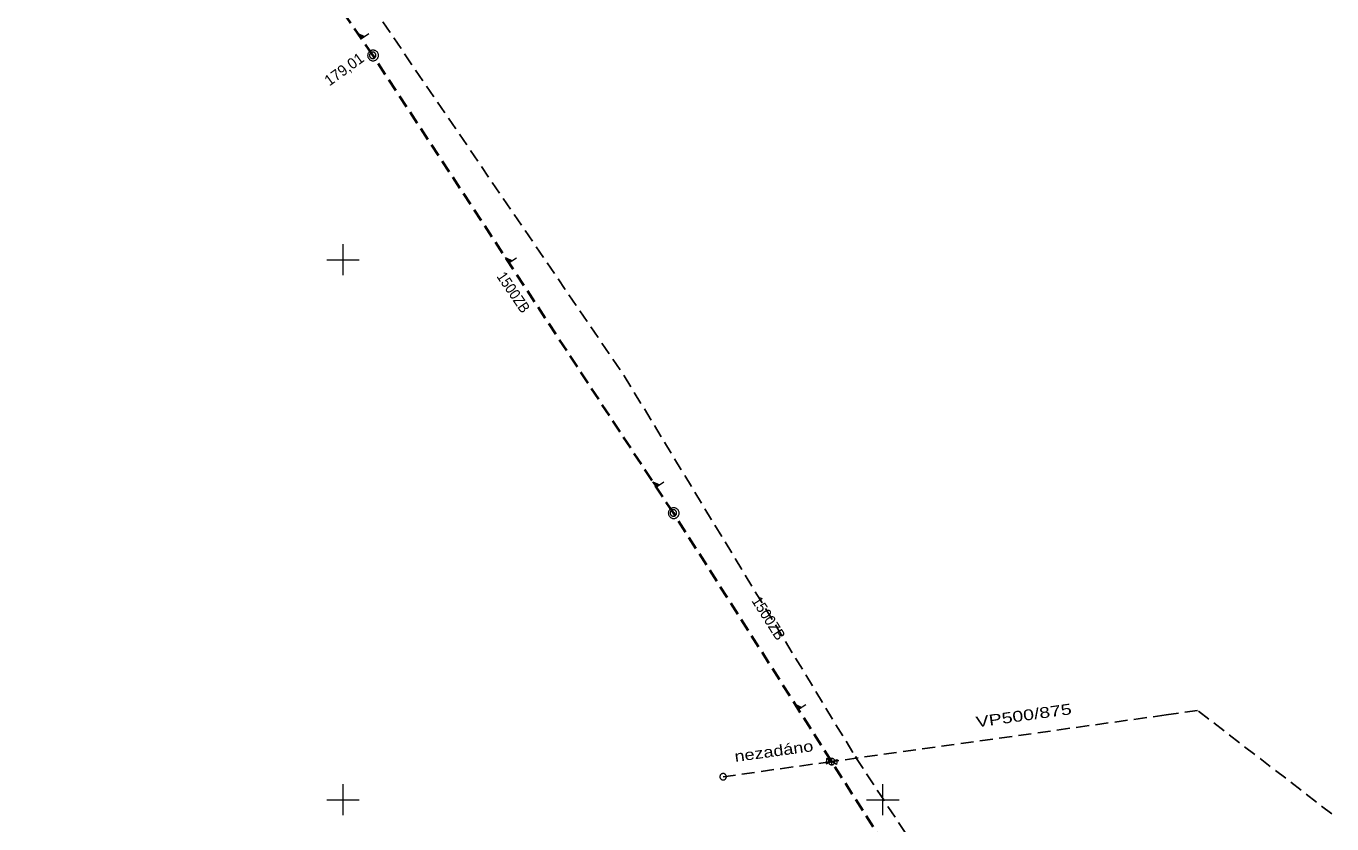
# Model space of a CAD drawing. Extents: x -740851 to -738888, y -1041382 to -1040235.
# Drawn here: x -739579.3 to -739458.4, y -1040852.2 to -1040778.4 of the extents above; entities that cross this region are included whole.
import ezdxf

# ---------------------------------------------------------------- set-up
doc = ezdxf.new("R2010")
doc.units = 0
doc.header["$LTSCALE"] = 0.4
doc.linetypes.add('MEDIUM_DASHED', pattern=[4.5, 3, -1.5])
for name, color, linetype, lineweight in [('1', 7, 'Continuous', 13), ('18', 7, 'Continuous', 13), ('19', 7, 'Continuous', 25), ('8', 7, 'Continuous', 13)]:
    doc.layers.add(name, color=color, linetype=linetype, lineweight=lineweight)

msp = doc.modelspace()

# ---------------------------------------------------------------- linework, layer by layer
at = {"layer": '1'}
for p, q in [((-739550, -1040798.571), (-739550, -1040801.429)), ((-739551.48, -1040800), (-739548.48, -1040800)), ((-739550, -1040848.571), (-739550, -1040851.429)), ((-739500, -1040848.571), (-739500, -1040851.429)), ((-739551.48, -1040850), (-739548.48, -1040850)), ((-739501.48, -1040850), (-739498.48, -1040850))]:
    msp.add_line(p, q, dxfattribs=at)
at = {"layer": '18', "linetype": 'MEDIUM_DASHED', "lineweight": 40}
for p, q in [((-739547.23, -1040781.07), (-739576.27, -1040738.69)), ((-739519.38, -1040823.45), (-739547.23, -1040781.07)), ((-739504.725, -1040846.471), (-739519.38, -1040823.45)), ((-739487.34, -1040873.78), (-739504.725, -1040846.471))]:
    msp.add_line(p, q, dxfattribs=at)
at = {"layer": '18'}
for q in [(-739504.75, -1040846.788), (-739504.703, -1040846.202)]:
    msp.add_line((-739504.725, -1040846.471), q, dxfattribs=at)
for points in [[(-739547.601, -1040779.085), (-739548.272, -1040779.545), (-739548.601, -1040779.066), (-739547.969, -1040779.338)], [(-739548.061, -1040779.349), (-739548.256, -1040779.483), (-739548.466, -1040779.177), (-739548.059, -1040779.352)], [(-739548.156, -1040779.362), (-739548.253, -1040779.429), (-739548.361, -1040779.272), (-739548.153, -1040779.365)], [(-739533.917, -1040799.841), (-739534.598, -1040800.289), (-739534.917, -1040799.803), (-739534.291, -1040800.087)], [(-739534.383, -1040800.096), (-739534.581, -1040800.226), (-739534.785, -1040799.916), (-739534.381, -1040800.099)], [(-739534.478, -1040800.107), (-739534.577, -1040800.172), (-739534.682, -1040800.013), (-739534.476, -1040800.11)], [(-739520.27, -1040820.608), (-739520.951, -1040821.056), (-739521.27, -1040820.57), (-739520.644, -1040820.854)], [(-739520.736, -1040820.863), (-739520.934, -1040820.993), (-739521.138, -1040820.683), (-739520.734, -1040820.866)], [(-739520.831, -1040820.874), (-739520.93, -1040820.939), (-739521.034, -1040820.78), (-739520.829, -1040820.877)], [(-739507.098, -1040841.222), (-739507.785, -1040841.66), (-739508.098, -1040841.169), (-739507.475, -1040841.463)], [(-739507.567, -1040841.47), (-739507.767, -1040841.598), (-739507.967, -1040841.284), (-739507.565, -1040841.474)], [(-739507.662, -1040841.48), (-739507.762, -1040841.544), (-739507.865, -1040841.383), (-739507.66, -1040841.483)]]:
    msp.add_lwpolyline(points, dxfattribs=at)
for points in [[(-739546.7, -1040781.08), (-739546.71, -1040781.03), (-739546.71, -1040780.98), (-739546.73, -1040780.93), (-739546.75, -1040780.88), (-739546.77, -1040780.83), (-739546.8, -1040780.79), (-739546.83, -1040780.75), (-739546.87, -1040780.71), (-739546.91, -1040780.68), (-739546.95, -1040780.65), (-739547, -1040780.63), (-739547.05, -1040780.61), (-739547.1, -1040780.59), (-739547.15, -1040780.59), (-739547.2, -1040780.58), (-739547.25, -1040780.59), (-739547.3, -1040780.59), (-739547.35, -1040780.61), (-739547.4, -1040780.63), (-739547.45, -1040780.65), (-739547.49, -1040780.68), (-739547.53, -1040780.71), (-739547.57, -1040780.75), (-739547.6, -1040780.79), (-739547.63, -1040780.83), (-739547.65, -1040780.88), (-739547.67, -1040780.93), (-739547.69, -1040780.98), (-739547.69, -1040781.03), (-739547.7, -1040781.08), (-739547.69, -1040781.13), (-739547.69, -1040781.18), (-739547.67, -1040781.23), (-739547.65, -1040781.28), (-739547.63, -1040781.33), (-739547.6, -1040781.37), (-739547.57, -1040781.41), (-739547.53, -1040781.45), (-739547.49, -1040781.48), (-739547.45, -1040781.51), (-739547.4, -1040781.53), (-739547.35, -1040781.55), (-739547.3, -1040781.57), (-739547.25, -1040781.57), (-739547.2, -1040781.58), (-739547.15, -1040781.57), (-739547.1, -1040781.57), (-739547.05, -1040781.55), (-739547, -1040781.53), (-739546.95, -1040781.51), (-739546.91, -1040781.48), (-739546.87, -1040781.45), (-739546.83, -1040781.41), (-739546.8, -1040781.37), (-739546.77, -1040781.33), (-739546.75, -1040781.28), (-739546.73, -1040781.23), (-739546.71, -1040781.18), (-739546.71, -1040781.13)], [(-739546.93, -1040781.07), (-739546.93, -1040781.04), (-739546.936, -1040781.01), (-739546.942, -1040780.98), (-739546.954, -1040780.95), (-739546.972, -1040780.92), (-739546.99, -1040780.896), (-739547.008, -1040780.872), (-739547.032, -1040780.848), (-739547.056, -1040780.83), (-739547.08, -1040780.812), (-739547.11, -1040780.794), (-739547.14, -1040780.782), (-739547.17, -1040780.776), (-739547.2, -1040780.77), (-739547.23, -1040780.77), (-739547.26, -1040780.77), (-739547.29, -1040780.776), (-739547.32, -1040780.782), (-739547.35, -1040780.794), (-739547.38, -1040780.812), (-739547.404, -1040780.83), (-739547.428, -1040780.848), (-739547.452, -1040780.872), (-739547.47, -1040780.896), (-739547.488, -1040780.92), (-739547.506, -1040780.95), (-739547.518, -1040780.98), (-739547.524, -1040781.01), (-739547.53, -1040781.04), (-739547.53, -1040781.07), (-739547.53, -1040781.1), (-739547.524, -1040781.13), (-739547.518, -1040781.16), (-739547.506, -1040781.19), (-739547.488, -1040781.22), (-739547.47, -1040781.244), (-739547.452, -1040781.268), (-739547.428, -1040781.292), (-739547.404, -1040781.31), (-739547.38, -1040781.328), (-739547.35, -1040781.346), (-739547.32, -1040781.358), (-739547.29, -1040781.364), (-739547.26, -1040781.37), (-739547.23, -1040781.37), (-739547.2, -1040781.37), (-739547.17, -1040781.364), (-739547.14, -1040781.358), (-739547.11, -1040781.346), (-739547.08, -1040781.328), (-739547.056, -1040781.31), (-739547.032, -1040781.292), (-739547.008, -1040781.268), (-739546.99, -1040781.244), (-739546.972, -1040781.22), (-739546.954, -1040781.19), (-739546.942, -1040781.16), (-739546.936, -1040781.13), (-739546.93, -1040781.1)], [(-739518.85, -1040823.46), (-739518.86, -1040823.41), (-739518.86, -1040823.36), (-739518.88, -1040823.31), (-739518.9, -1040823.26), (-739518.92, -1040823.21), (-739518.95, -1040823.17), (-739518.98, -1040823.13), (-739519.02, -1040823.09), (-739519.06, -1040823.06), (-739519.1, -1040823.03), (-739519.15, -1040823.01), (-739519.2, -1040822.99), (-739519.25, -1040822.97), (-739519.3, -1040822.97), (-739519.35, -1040822.96), (-739519.4, -1040822.97), (-739519.45, -1040822.97), (-739519.5, -1040822.99), (-739519.55, -1040823.01), (-739519.6, -1040823.03), (-739519.64, -1040823.06), (-739519.68, -1040823.09), (-739519.72, -1040823.13), (-739519.75, -1040823.17), (-739519.78, -1040823.21), (-739519.8, -1040823.26), (-739519.82, -1040823.31), (-739519.84, -1040823.36), (-739519.84, -1040823.41), (-739519.85, -1040823.46), (-739519.84, -1040823.51), (-739519.84, -1040823.56), (-739519.82, -1040823.61), (-739519.8, -1040823.66), (-739519.78, -1040823.71), (-739519.75, -1040823.75), (-739519.72, -1040823.79), (-739519.68, -1040823.83), (-739519.64, -1040823.86), (-739519.6, -1040823.89), (-739519.55, -1040823.91), (-739519.5, -1040823.93), (-739519.45, -1040823.95), (-739519.4, -1040823.95), (-739519.35, -1040823.96), (-739519.3, -1040823.95), (-739519.25, -1040823.95), (-739519.2, -1040823.93), (-739519.15, -1040823.91), (-739519.1, -1040823.89), (-739519.06, -1040823.86), (-739519.02, -1040823.83), (-739518.98, -1040823.79), (-739518.95, -1040823.75), (-739518.92, -1040823.71), (-739518.9, -1040823.66), (-739518.88, -1040823.61), (-739518.86, -1040823.56), (-739518.86, -1040823.51)], [(-739519.08, -1040823.45), (-739519.08, -1040823.42), (-739519.086, -1040823.39), (-739519.092, -1040823.36), (-739519.104, -1040823.33), (-739519.122, -1040823.3), (-739519.14, -1040823.276), (-739519.158, -1040823.252), (-739519.182, -1040823.228), (-739519.206, -1040823.21), (-739519.23, -1040823.192), (-739519.26, -1040823.174), (-739519.29, -1040823.162), (-739519.32, -1040823.156), (-739519.35, -1040823.15), (-739519.38, -1040823.15), (-739519.41, -1040823.15), (-739519.44, -1040823.156), (-739519.47, -1040823.162), (-739519.5, -1040823.174), (-739519.53, -1040823.192), (-739519.554, -1040823.21), (-739519.578, -1040823.228), (-739519.602, -1040823.252), (-739519.62, -1040823.276), (-739519.638, -1040823.3), (-739519.656, -1040823.33), (-739519.668, -1040823.36), (-739519.674, -1040823.39), (-739519.68, -1040823.42), (-739519.68, -1040823.45), (-739519.68, -1040823.48), (-739519.674, -1040823.51), (-739519.668, -1040823.54), (-739519.656, -1040823.57), (-739519.638, -1040823.6), (-739519.62, -1040823.624), (-739519.602, -1040823.648), (-739519.578, -1040823.672), (-739519.554, -1040823.69), (-739519.53, -1040823.708), (-739519.5, -1040823.726), (-739519.47, -1040823.738), (-739519.44, -1040823.744), (-739519.41, -1040823.75), (-739519.38, -1040823.75), (-739519.35, -1040823.75), (-739519.32, -1040823.744), (-739519.29, -1040823.738), (-739519.26, -1040823.726), (-739519.23, -1040823.708), (-739519.206, -1040823.69), (-739519.182, -1040823.672), (-739519.158, -1040823.648), (-739519.14, -1040823.624), (-739519.122, -1040823.6), (-739519.104, -1040823.57), (-739519.092, -1040823.54), (-739519.086, -1040823.51), (-739519.08, -1040823.48)], [(-739504.264, -1040846.75), (-739505.186, -1040846.192), (-739505.225, -1040846.673), (-739504.225, -1040846.27)], [(-739504.887, -1040846.216), (-739504.912, -1040846.233), (-739504.935, -1040846.254), (-739504.957, -1040846.275), (-739504.976, -1040846.302), (-739504.991, -1040846.333), (-739505.002, -1040846.361), (-739505.013, -1040846.39), (-739505.02, -1040846.423), (-739505.022, -1040846.453), (-739505.025, -1040846.483), (-739505.024, -1040846.518), (-739505.018, -1040846.55), (-739505.007, -1040846.579), (-739504.996, -1040846.608), (-739504.979, -1040846.633), (-739504.963, -1040846.659), (-739504.942, -1040846.681), (-739504.921, -1040846.703), (-739504.894, -1040846.722), (-739504.863, -1040846.738), (-739504.834, -1040846.748), (-739504.806, -1040846.759), (-739504.773, -1040846.766), (-739504.743, -1040846.769), (-739504.713, -1040846.771), (-739504.678, -1040846.77), (-739504.646, -1040846.764), (-739504.617, -1040846.753), (-739504.588, -1040846.742), (-739504.563, -1040846.726), (-739504.537, -1040846.709), (-739504.515, -1040846.688), (-739504.493, -1040846.667), (-739504.474, -1040846.641), (-739504.458, -1040846.609), (-739504.447, -1040846.581), (-739504.437, -1040846.553), (-739504.429, -1040846.519), (-739504.427, -1040846.489), (-739504.425, -1040846.459), (-739504.426, -1040846.424), (-739504.432, -1040846.392), (-739504.443, -1040846.363), (-739504.454, -1040846.334), (-739504.47, -1040846.309), (-739504.486, -1040846.284), (-739504.508, -1040846.261), (-739504.529, -1040846.239), (-739504.555, -1040846.22), (-739504.587, -1040846.204), (-739504.615, -1040846.194), (-739504.643, -1040846.183), (-739504.677, -1040846.176), (-739504.707, -1040846.173), (-739504.737, -1040846.171), (-739504.772, -1040846.172), (-739504.804, -1040846.178), (-739504.833, -1040846.189), (-739504.861, -1040846.2)], [(-739504.887, -1040846.216), (-739504.912, -1040846.233), (-739504.935, -1040846.254), (-739504.957, -1040846.275), (-739504.976, -1040846.302), (-739504.991, -1040846.333), (-739505.002, -1040846.361), (-739505.013, -1040846.39), (-739505.02, -1040846.423), (-739505.022, -1040846.453), (-739505.025, -1040846.483), (-739505.024, -1040846.518), (-739505.018, -1040846.55), (-739505.007, -1040846.579), (-739504.996, -1040846.608), (-739504.979, -1040846.633), (-739504.963, -1040846.659), (-739504.942, -1040846.681), (-739504.921, -1040846.703), (-739504.894, -1040846.722), (-739504.863, -1040846.738), (-739504.834, -1040846.748), (-739504.806, -1040846.759), (-739504.773, -1040846.766), (-739504.743, -1040846.769), (-739504.713, -1040846.771), (-739504.678, -1040846.77), (-739504.646, -1040846.764), (-739504.617, -1040846.753), (-739504.588, -1040846.742), (-739504.563, -1040846.726), (-739504.537, -1040846.709), (-739504.515, -1040846.688), (-739504.493, -1040846.667), (-739504.474, -1040846.641), (-739504.458, -1040846.609), (-739504.447, -1040846.581), (-739504.437, -1040846.553), (-739504.429, -1040846.519), (-739504.427, -1040846.489), (-739504.425, -1040846.459), (-739504.426, -1040846.424), (-739504.432, -1040846.392), (-739504.443, -1040846.363), (-739504.454, -1040846.334), (-739504.47, -1040846.309), (-739504.486, -1040846.284), (-739504.508, -1040846.261), (-739504.529, -1040846.239), (-739504.555, -1040846.22), (-739504.587, -1040846.204), (-739504.615, -1040846.194), (-739504.643, -1040846.183), (-739504.677, -1040846.176), (-739504.707, -1040846.173), (-739504.737, -1040846.171), (-739504.772, -1040846.172), (-739504.804, -1040846.178), (-739504.833, -1040846.189), (-739504.861, -1040846.2)], [(-739515.068, -1040847.915), (-739515.064, -1040847.945), (-739515.054, -1040847.974), (-739515.044, -1040848.002), (-739515.028, -1040848.03), (-739515.006, -1040848.057), (-739514.985, -1040848.079), (-739514.964, -1040848.1), (-739514.937, -1040848.12), (-739514.911, -1040848.135), (-739514.885, -1040848.149), (-739514.853, -1040848.163), (-739514.821, -1040848.17), (-739514.791, -1040848.172), (-739514.761, -1040848.174), (-739514.731, -1040848.17), (-739514.701, -1040848.166), (-739514.673, -1040848.156), (-739514.644, -1040848.146), (-739514.616, -1040848.13), (-739514.589, -1040848.108), (-739514.568, -1040848.087), (-739514.546, -1040848.066), (-739514.526, -1040848.039), (-739514.512, -1040848.012), (-739514.497, -1040847.986), (-739514.484, -1040847.954), (-739514.476, -1040847.923), (-739514.474, -1040847.893), (-739514.472, -1040847.862), (-739514.476, -1040847.833), (-739514.481, -1040847.803), (-739514.491, -1040847.774), (-739514.501, -1040847.745), (-739514.517, -1040847.718), (-739514.539, -1040847.69), (-739514.56, -1040847.669), (-739514.581, -1040847.648), (-739514.608, -1040847.628), (-739514.634, -1040847.613), (-739514.66, -1040847.599), (-739514.692, -1040847.585), (-739514.723, -1040847.577), (-739514.754, -1040847.576), (-739514.784, -1040847.574), (-739514.814, -1040847.578), (-739514.843, -1040847.582), (-739514.872, -1040847.592), (-739514.901, -1040847.602), (-739514.929, -1040847.618), (-739514.956, -1040847.64), (-739514.977, -1040847.661), (-739514.998, -1040847.682), (-739515.019, -1040847.709), (-739515.033, -1040847.735), (-739515.047, -1040847.761), (-739515.061, -1040847.794), (-739515.069, -1040847.825), (-739515.071, -1040847.855), (-739515.072, -1040847.886)]]:
    msp.add_lwpolyline(points, close=True, dxfattribs=at)
at = {"layer": '19', "linetype": 'MEDIUM_DASHED'}
msp.add_lwpolyline([(-739458.386, -1040851.318), (-739470.819, -1040841.737), (-739473.748, -1040842.146), (-739504.725, -1040846.471), (-739514.772, -1040847.874)], dxfattribs=at)
at = {"layer": '8'}
for p, q in [((-739502.537, -1040846.084), (-739502.52, -1040846.073)), ((-739502.537, -1040846.084), (-739502.4, -1040846.117)), ((-739502.537, -1040846.084), (-739502.527, -1040846.101)), ((-739502.485, -1040846.169), (-739502.496, -1040846.152)), ((-739502.452, -1040846.032), (-739502.485, -1040846.169)), ((-739502.485, -1040846.169), (-739502.468, -1040846.159)), ((-739502.452, -1040846.032), (-739502.469, -1040846.042)), ((-739502.452, -1040846.032), (-739502.441, -1040846.049)), ((-739502.4, -1040846.117), (-739502.417, -1040846.128)), ((-739502.4, -1040846.117), (-739502.41, -1040846.1))]:
    msp.add_line(p, q, dxfattribs=at)
at = {"layer": '8', "linetype": 'MEDIUM_DASHED', "lineweight": 25}
msp.add_lwpolyline([(-739693.286, -1040576.71), (-739686.808, -1040583.233), (-739625.283, -1040665.839), (-739571.664, -1040740.804), (-739523.94, -1040810.745), (-739502.47, -1040846.1), (-739496.554, -1040855.122)], dxfattribs=at)
at = {"layer": '8'}
msp.add_lwpolyline([(-739502.443, -1040846.143), (-739502.438, -1040846.14), (-739502.435, -1040846.137), (-739502.431, -1040846.134), (-739502.428, -1040846.129), (-739502.425, -1040846.124), (-739502.423, -1040846.119), (-739502.421, -1040846.115), (-739502.42, -1040846.109), (-739502.419, -1040846.104), (-739502.419, -1040846.099), (-739502.419, -1040846.094), (-739502.42, -1040846.088), (-739502.422, -1040846.083), (-739502.423, -1040846.079), (-739502.426, -1040846.074), (-739502.428, -1040846.07), (-739502.432, -1040846.066), (-739502.435, -1040846.063), (-739502.44, -1040846.059), (-739502.445, -1040846.057), (-739502.449, -1040846.055), (-739502.454, -1040846.053), (-739502.46, -1040846.052), (-739502.465, -1040846.051), (-739502.47, -1040846.051), (-739502.475, -1040846.051), (-739502.481, -1040846.052), (-739502.486, -1040846.053), (-739502.49, -1040846.055), (-739502.495, -1040846.058), (-739502.499, -1040846.06), (-739502.503, -1040846.064), (-739502.506, -1040846.067), (-739502.51, -1040846.071), (-739502.512, -1040846.077), (-739502.514, -1040846.081), (-739502.516, -1040846.086), (-739502.517, -1040846.091), (-739502.518, -1040846.096), (-739502.518, -1040846.101), (-739502.518, -1040846.107), (-739502.517, -1040846.112), (-739502.516, -1040846.117), (-739502.514, -1040846.122), (-739502.511, -1040846.126), (-739502.509, -1040846.131), (-739502.505, -1040846.134), (-739502.502, -1040846.138), (-739502.498, -1040846.141), (-739502.492, -1040846.144), (-739502.488, -1040846.146), (-739502.483, -1040846.148), (-739502.478, -1040846.149), (-739502.473, -1040846.15), (-739502.468, -1040846.15), (-739502.462, -1040846.15), (-739502.457, -1040846.149), (-739502.452, -1040846.147), (-739502.447, -1040846.146)], close=True, dxfattribs=at)

# ---------------------------------------------------------------- texts
at = {"layer": '18'}
msp.add_text('179,01', height=1, rotation=35.958, dxfattribs=at).set_placement((-739551.245, -1040783.963))
for s, rotation, width, p in [('1500ZB', 304.311, 0.9, (-739535.793, -1040801.554)), ('1500ZB', 302.482, 0.95, (-739512.175, -1040831.584)), ('VP500/875 ', 7.948, 1.35, (-739491.286, -1040843.31)), ('nezadáno ', 7.948, 1.25, (-739513.645, -1040846.509))]:
    msp.add_text(s, height=1, rotation=rotation, dxfattribs=dict(at, width=width)).set_placement(p)

doc.saveas('drawing.dxf')
